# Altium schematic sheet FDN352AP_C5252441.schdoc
size 127 x 101 mm
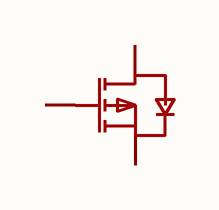
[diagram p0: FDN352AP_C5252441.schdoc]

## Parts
Q?  fdn352ap(umw)  [SOT-23-3_L2.9-W1.3-P1.90-LS2.4-BR]  (value not drawn)

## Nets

Not connected (* = marked no-connect by the designer): Q? 1(G) 2(S) 3(D)

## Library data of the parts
Q? = fdn352ap(umw): 数量:1个P沟道;漏源电压(Vdss):30V;连续漏极电流(Id):1.3A;导通电阻(RDS(on)):150mΩ@10V；250mΩ@4.5V;耗散功率(Pd):500mW;阈值电压(Vgs(th)):2V;; Manufacturer: UMW(友台半导体); Symbol: FDN352AP_C5252441; AddInBom: yes; ModelId: c62791f0466c4ae2a892c056b845b0ca; ModelName: SOT-23-3P_L2.9-W1.3-H1.0-LS2.4-P0.95; ModelTransform: 98.425,114.173,0,180,0,0,0.0005,-0.0005,0; Number: 1个P沟道; Drain to Source Voltage: 30V; Current - Continuous Drain(Id): 1.3A; Pd - Power Dissipation: 500mW; Gate Threshold Voltage (Vgs(th)): 2V; Gate Charge(Qg): 1.4nC@10V; Input Capacitance(Ciss): 150pF; Reverse Transfer Capacitance (Crss@Vds): 20pF; Output Capacitance(Coss): 40pF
